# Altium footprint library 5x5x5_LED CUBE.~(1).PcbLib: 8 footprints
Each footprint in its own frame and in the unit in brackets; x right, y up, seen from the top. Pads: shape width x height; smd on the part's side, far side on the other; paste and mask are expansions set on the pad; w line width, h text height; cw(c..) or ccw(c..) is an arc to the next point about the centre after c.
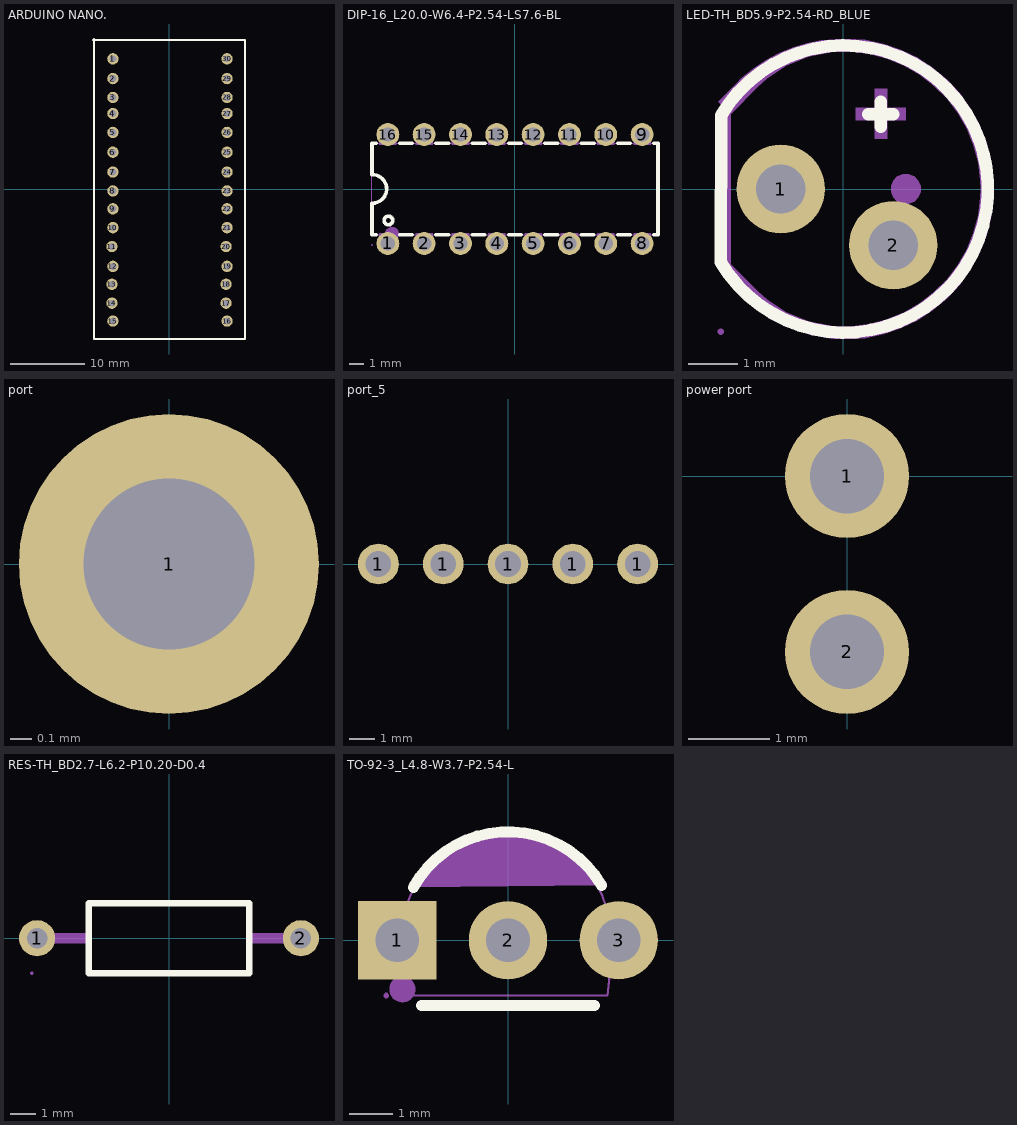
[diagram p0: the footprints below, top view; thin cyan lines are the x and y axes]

## ARDUINO NANO. [mil]
pads (30):
  round 60 hole 36 paste-99999 mask+2: 1(-297.5,690) 2(-297.5,585) 3(-297.5,485) 4(-297.5,400) 5(-297.5,300) 6(-297.5,195) 7(-297.5,90) 8(-297.5,-10) 9(-297.5,-105) 10(-297.5,-205) 11(-302.5,-305) 12(-297.5,-410) 13(-302.5,-505) 14(-302.5,-605) 15(-297.5,-700) 16(307.5,-700) 17(302.5,-605) 18(302.5,-505) 19(307.5,-410) 20(302.5,-305) 21(307.5,-205) 22(307.5,-105) 23(307.5,-10) 24(307.5,90) 25(307.5,195) 26(307.5,300) 27(307.5,400) 28(307.5,485) 29(307.5,585) 30(307.5,690)
Top Overlay:
  lines w10: -402.5,790 402.5,790 402.5,-795 -397.5,-795 -397.5,795

## DIP-16_L20.0-W6.4-P2.54-LS7.6-BL [mm]
pads (16):
  round 1.6 hole 1: 1(-8.89,-3.81) 2(-6.35,-3.81) 3(-3.81,-3.81) 4(-1.27,-3.81) 5(1.27,-3.81) 6(3.81,-3.81) 7(6.35,-3.81) 8(8.89,-3.81) 9(8.89,3.81) 10(6.35,3.81) 11(3.81,3.81) 12(1.27,3.81) 13(-1.27,3.81) 14(-3.81,3.81) 15(-6.35,3.81) 16(-8.89,3.81)
Top Overlay:
  circle w0.254: c-8.85,-2.2 r0.3
  lines w0.254: -10,-1 -10,-3.2 -9.721,-3.2 ; -10,0.998 -10,3.198 -9.719,3.198 ; -10,1 cw(c-9.975,0) -9.95,-1 ; -8.061,3.198 -7.179,3.198 ; -8.059,-3.2 -7.181,-3.2 ; -5.521,3.198 -4.639,3.198 ; -5.519,-3.2 -4.641,-3.2 ; -2.981,3.198 -2.099,3.198 ; -2.979,-3.2 -2.101,-3.2 ; -0.441,3.198 0.441,3.198 ; -0.439,-3.2 0.439,-3.2 ; 2.099,3.198 2.981,3.198 ; 2.101,-3.2 2.979,-3.2 ; 4.639,3.198 5.521,3.198 ; 4.641,-3.2 5.519,-3.2 ; 7.179,3.198 8.061,3.198 ; 7.181,-3.2 8.059,-3.2 ; 9.719,3.198 10,3.198 ; 9.721,-3.2 10,-3.2 10,3.2
Mechanical 6:
  circle w0.5: c-8.6,-3.15 r0.25
Mechanical 15:
  drawing of 37 lines, arcs and shapes, not listed

## LED-TH_BD5.9-P2.54-RD_BLUE [mm]
pads (2):
  round 1.8 hole 1 paste-2539.97 mask+0.05: 1(-1.27,0) 2(1.016,-1.143)
Top Overlay:
  lines w0.254: 0.508,1.524 1.016,1.524 ; 0.762,1.27 0.762,1.778 ; -2.489,-1.489 ccw(c0.02,0) -2.483,1.499 -2.489,-1.489
Mechanical 6:
  region: -2.286,1.524 -1.734,2.076 -1.556,2.237 -1.156,2.504 -0.712,2.688 -0.24,2.782 0,2.794 0.183,2.788 0.545,2.74 0.898,2.646 1.236,2.506 1.552,2.323 1.842,2.101 2.101,1.842 2.323,1.552 2.506,1.236 2.646,0.898 2.74,0.545 2.788,0.183 2.794,0 2.788,-0.183 2.74,-0.545 2.646,-0.898 2.506,-1.236 2.323,-1.552 2.101,-1.842 1.842,-2.101 1.552,-2.323 1.236,-2.506 0.898,-2.646 0.545,-2.74 0.183,-2.788 0,-2.794 -0.24,-2.782 -0.712,-2.688 -1.156,-2.504 -1.556,-2.237 -1.734,-2.076 -2.286,-1.524 -2.54,-1.524 -1.734,-2.33 -1.564,-2.5 -1.162,-2.769 -0.715,-2.954 -0.242,-3.048 0,-3.048 0.254,-3.048 0.443,-3.032 0.814,-2.954 1.172,-2.83 1.513,-2.663 1.83,-2.456 2.119,-2.21 2.375,-1.93 2.595,-1.621 2.774,-1.287 2.911,-0.934 3.003,-0.566 3.049,-0.19 3.048,0 3.049,0.19 3.003,0.566 2.911,0.934 2.774,1.287 2.595,1.621 2.375,1.93 2.119,2.21 1.83,2.456 1.513,2.663 1.172,2.83 0.814,2.954 0.443,3.032 0.254,3.048 0,3.048 -0.151,3.048 -0.45,3.018 -0.746,2.96 -1.034,2.872 -1.312,2.757 -1.578,2.615 -1.829,2.448 -2.062,2.256 -2.168,2.15 -2.54,1.778
  region: -2.54,-1.524 -2.286,-1.524 -2.286,1.524 -2.54,1.524
  region: 0.89,1.019 0.89,2.035 0.636,2.035 0.636,1.019
  region: 0.254,1.397 1.27,1.397 1.27,1.651 0.254,1.651
Mechanical 15:
  region: -0.97,0 -0.97,-0.06 -1.016,-0.17 -1.1,-0.254 -1.21,-0.3 -1.33,-0.3 -1.44,-0.254 -1.524,-0.17 -1.57,-0.06 -1.57,0 -1.57,0.06 -1.524,0.17 -1.44,0.254 -1.33,0.3 -1.21,0.3 -1.1,0.254 -1.016,0.17 -0.97,0.06
  region: 1.57,0 1.57,-0.06 1.524,-0.17 1.44,-0.254 1.33,-0.3 1.21,-0.3 1.1,-0.254 1.016,-0.17 0.97,-0.06 0.97,0 0.97,0.06 1.016,0.17 1.1,0.254 1.21,0.3 1.33,0.3 1.44,0.254 1.524,0.17 1.57,0.06
  region: -2.43,-2.9 -2.43,-2.925 -2.465,-2.96 -2.515,-2.96 -2.55,-2.925 -2.55,-2.9 -2.55,-2.875 -2.515,-2.84 -2.465,-2.84 -2.43,-2.875
  lines w0.051: -2.49,-1.49 -2.49,1.5 -2.22,1.88 -1.89,2.21 -1.5,2.49 -1.08,2.69 -0.63,2.83 -0.18,2.9 0.01,2.9 cw(c0.01,0.03) 2.88,0.03 2.88,-0.01 2.88,-0.02 cw(c0.01,-0.02) 0.01,-2.89 -0.17,-2.9 -0.63,-2.83 -1.07,-2.69 -1.5,-2.49 -1.88,-2.22 -2.22,-1.88 -2.49,-1.49
3D body "LED 5mm.STEP": height 8.8, standoff -27, extent -2.609,-1.992 3.371,3.508

## port [mm]
pads (1):
  round 1.4 hole 0.8 copper offset 0,0: 1(0,0)

## port_5 [mm]
pads (5):
  round 1.6 hole 1: 1(-5.08,0) 1(-2.54,0) 1(0,0) 1(2.54,0) 1(5.08,0)

## power port [mil]
pads (2):
  round 60 hole 36 paste-99999 mask+2: 1(0,0) 2(0,-85)

## RES-TH_BD2.7-L6.2-P10.20-D0.4 [mm]
pads (2):
  round 1.4 hole 0.8 copper offset 0,0: 1(-5.1,0) 2(5.1,0)
Top Overlay:
  lines w0.254: -3.1,-1.35 -3.1,1.35 3.1,1.35 3.1,-1.35 -3.1,-1.35
Mechanical 15:
  region: -3.05,0.2 -3.05,-0.2 -5.3,-0.2 -5.3,0.2
  region: 3.05,-0.2 3.05,0.2 5.3,0.2 5.3,-0.2
  region: 5.3,0 5.3,-0.04 5.27,-0.113 5.213,-0.17 5.14,-0.2 5.06,-0.2 4.987,-0.17 4.93,-0.113 4.9,-0.04 4.9,0 4.9,0.04 4.93,0.113 4.987,0.17 5.06,0.2 5.14,0.2 5.213,0.17 5.27,0.113 5.3,0.04
  region: -4.9,0 -4.9,-0.04 -4.93,-0.113 -4.987,-0.17 -5.06,-0.2 -5.14,-0.2 -5.213,-0.17 -5.27,-0.113 -5.3,-0.04 -5.3,0 -5.3,0.04 -5.27,0.113 -5.213,0.17 -5.14,0.2 -5.06,0.2 -4.987,0.17 -4.93,0.113 -4.9,0.04
  region: -5.24,-1.35 -5.24,-1.375 -5.275,-1.41 -5.325,-1.41 -5.36,-1.375 -5.36,-1.35 -5.36,-1.325 -5.325,-1.29 -5.275,-1.29 -5.24,-1.325
  lines w0.051: -3.1,-1.35 3.1,-1.35 3.1,1.35 -3.1,1.35 -3.1,-1.35

## TO-92-3_L4.8-W3.7-P2.54-L [mm]
pads (3):
  rect 1.8x1.8 hole 1: 1(-2.54,0)
  round 1.8 hole 1: 2(0,0) 3(2.54,0)
Top Overlay:
  lines w0.254: -2.171,1.211 cw(c0,0) 2.144,1.26 ; -1.98,-1.5 1.98,-1.5
Mechanical 6:
  circle w0.3: c-2.422,-1.124 r0.15
  region: 2.144,1.26 2.033,1.448 1.75,1.78 1.413,2.058 1.033,2.272 0.621,2.418 0.19,2.489 -0.246,2.484 -0.675,2.403 -1.083,2.249 -1.459,2.026 -1.789,1.74 -2.065,1.402 -2.171,1.211
Mechanical 15:
  region: -2.73,-1.271 -2.73,-1.296 -2.765,-1.331 -2.815,-1.331 -2.85,-1.296 -2.85,-1.271 -2.85,-1.246 -2.815,-1.211 -2.765,-1.211 -2.73,-1.246
  region: -2.29,-0.2 -2.79,-0.2 -2.79,0.2 -2.29,0.2
  region: 0.25,-0.2 -0.25,-0.2 -0.25,0.2 0.25,0.2
  region: 2.79,-0.2 2.29,-0.2 2.29,0.2 2.79,0.2
  lines w0.051: -2.448,0.067 -2.448,0.069 cw(c-0.164,0.069) -1.779,1.684 -1.646,1.817 -1.613,1.85 cw(c-0.142,0.378) -0.142,2.459 0.067,2.459 cw(c0.067,0.253) 1.627,1.813 cw(c-0.131,0.055) 2.355,0.055 2.355,-0.566 2.285,-1.271 2.284,-1.27 -2.26,-1.27 -2.448,0.067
